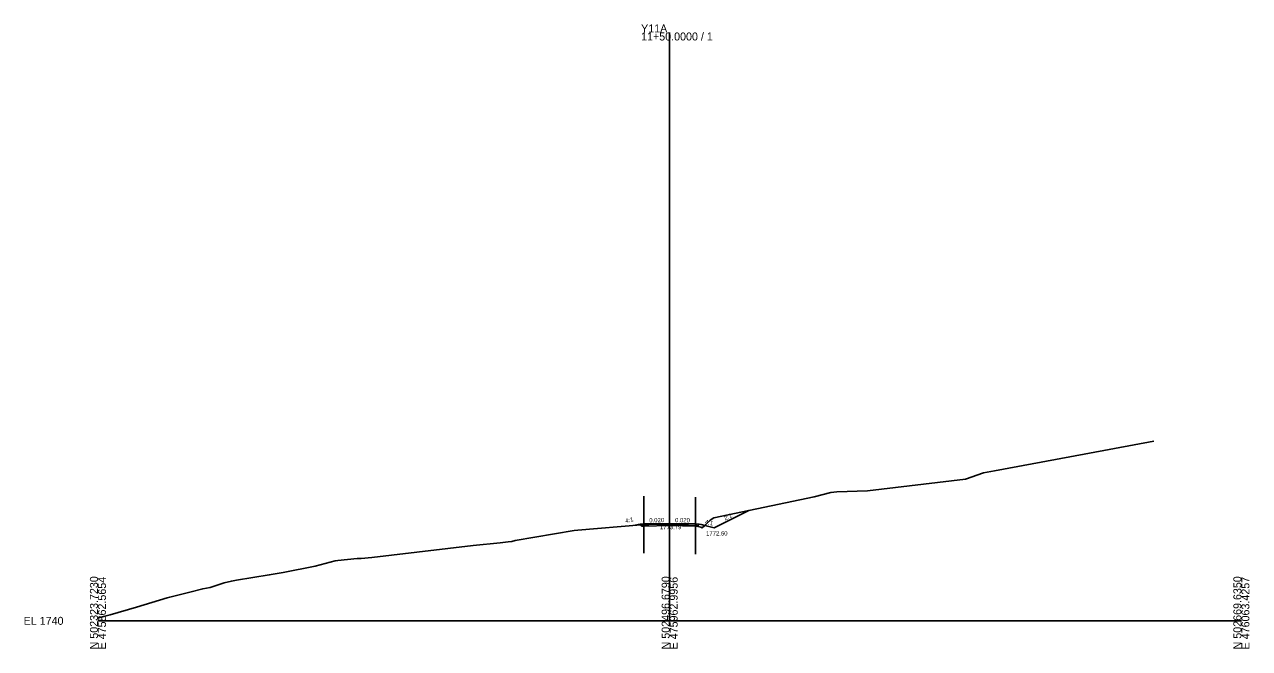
# Model space of a CAD drawing. Extents: x -26 to 403, y -10 to 5098.
# Drawn here: x -25.7 to 402.8, y 1490.3 to 1708.8 of the extents above; entities that cross this region are included whole.
import ezdxf

# ---------------------------------------------------------------- set-up
doc = ezdxf.new("R2010")
doc.units = 0
for name, color, linetype in [('Exist Cross Section Cell', 7, 'Continuous'), ('Exist XS Center Line Elevation Label', 7, 'Continuous'), ('Exist XS Ground Line', 7, 'Continuous'), ('Prop XS Ditch Slope Text', 7, 'Continuous'), ('Prop XS Ditch Standard Text', 7, 'Continuous'), ('Prop XS Dump Level', 7, 'Continuous'), ('Prop XS Earthwork Shape', 7, 'Continuous'), ('Prop XS EOT Tick Mark', 7, 'Continuous'), ('Prop XS Finish Grade', 7, 'Continuous'), ('Prop XS Finish Grade Earthwork', 7, 'Continuous'), ('Prop XS Finish Grade Pavement', 7, 'Continuous'), ('Prop XS Hydro Typical Ditch Data', 7, 'Continuous'), ('Prop XS Pvmt Edge Slope', 7, 'Continuous'), ('Prop XS SE Text', 7, 'Continuous'), ('Prop XS Shoulder Borrow Shape', 7, 'Continuous'), ('Prop XS Side Slope Text', 7, 'Continuous'), ('Prop XS Subgrade Earthwork', 7, 'Continuous'), ('Scratch_Level_5', 7, 'Continuous')]:
    doc.layers.add(name, color=color, linetype=linetype)

msp = doc.modelspace()

# ---------------------------------------------------------------- linework, layer by layer
at = {"layer": 'Exist Cross Section Cell'}
for p, q in [((200, 1500), (200, 1705.98)), ((0, 1500), (200, 1500)), ((200, 1500), (400, 1500))]:
    msp.add_line(p, q, dxfattribs=at)
at = {"layer": 'Exist XS Ground Line'}
msp.add_lwpolyline([(0, 1501.01), (0.33, 1501.08), (1.97, 1501.51), (4.29, 1502.13), (13.53, 1504.8), (24.21, 1508.07), (25.1, 1508.33), (32.09, 1509.99), (36.67, 1511.26), (39.21, 1511.71), (44.13, 1513.27), (46.72, 1513.9), (48.52, 1514.27), (59.91, 1516.09), (64.74, 1516.96), (75.99, 1519.19), (82.93, 1520.96), (83.96, 1521.13), (90.63, 1521.8), (92.06, 1521.84), (95.76, 1522.21), (102.66, 1522.98), (131.21, 1526.32), (140.76, 1527.35), (143.51, 1527.65), (144.78, 1527.79), (145.95, 1528.07), (166.63, 1531.67), (167.88, 1531.79), (189.95, 1533.66), (195.56, 1533.8), (198.46, 1533.87), (200, 1533.79), (208.8, 1533.35), (209.94, 1533.06), (210.85, 1532.76), (211.39, 1532.6), (214.18, 1535.23), (215.42, 1536.06), (250.5, 1543.44), (256.42, 1544.92), (258.52, 1545.16), (269.15, 1545.56), (303.48, 1549.6), (309.76, 1551.81), (313.64, 1552.56), (339.98, 1557.38), (369.37, 1562.86)], dxfattribs=at)
at = {"layer": 'Prop XS Dump Level'}
for p, q in [((191, 1533.91), (200, 1534.09)), ((200, 1534.09), (209, 1533.91))]:
    msp.add_line(p, q, dxfattribs=at)
at = {"layer": 'Prop XS Earthwork Shape'}
for points in [[(215.6, 1532.6), (227.7, 1538.65), (215.42, 1536.06), (214.18, 1535.23), (212.28, 1533.43)], [(189, 1533.75), (187.99, 1533.5), (189.81, 1533.65), (189.66, 1533.8)], [(189.81, 1533.65), (189.95, 1533.66), (195.56, 1533.8), (198.46, 1533.87), (200, 1533.79), (208.8, 1533.35), (209.4, 1533.19), (209, 1533.2), (200, 1533.38), (191, 1533.2), (190.28, 1533.19)], [(211, 1533.75), (212.28, 1533.43), (211.39, 1532.6), (210.85, 1532.76), (209.94, 1533.06), (209.4, 1533.19), (209.72, 1533.19), (210.34, 1533.8)]]:
    msp.add_lwpolyline(points, close=True, dxfattribs=at)
at = {"layer": 'Prop XS EOT Tick Mark'}
for p, q in [((191, 1533.91), (191, 1534.91)), ((209, 1533.91), (209, 1534.91))]:
    msp.add_line(p, q, dxfattribs=at)
at = {"layer": 'Prop XS Finish Grade'}
for p, q in [((191, 1533.91), (189.66, 1533.8)), ((209, 1533.91), (210.34, 1533.8))]:
    msp.add_line(p, q, dxfattribs=at)
at = {"layer": 'Prop XS Finish Grade Earthwork'}
for p, q in [((215.6, 1532.6), (227.7, 1538.65)), ((189, 1533.75), (187.99, 1533.5)), ((189.66, 1533.8), (189, 1533.75)), ((210.34, 1533.8), (211, 1533.75)), ((211, 1533.75), (215.6, 1532.6))]:
    msp.add_line(p, q, dxfattribs=at)
at = {"layer": 'Prop XS Finish Grade Pavement'}
for p, q in [((191, 1533.91), (200, 1534.09)), ((200, 1534.09), (209, 1533.91))]:
    msp.add_line(p, q, dxfattribs=at)
at = {"layer": 'Prop XS Hydro Typical Ditch Data'}
for p, q in [((215.6, 1532.6), (227.7, 1538.65)), ((211, 1533.75), (215.6, 1532.6))]:
    msp.add_line(p, q, dxfattribs=at)
at = {"layer": 'Prop XS Pvmt Edge Slope'}
for p, q in [((191, 1533.91), (190.28, 1533.19)), ((209, 1533.91), (209.72, 1533.19))]:
    msp.add_line(p, q, dxfattribs=at)
at = {"layer": 'Prop XS Shoulder Borrow Shape'}
for points in [[(191, 1533.91), (190.28, 1533.19), (189.66, 1533.8)], [(209.72, 1533.19), (210.34, 1533.8), (209, 1533.91)]]:
    msp.add_lwpolyline(points, close=True, dxfattribs=at)
at = {"layer": 'Prop XS Subgrade Earthwork'}
for p, q in [((190.28, 1533.19), (189.66, 1533.8)), ((191, 1533.2), (190.28, 1533.19)), ((200, 1533.38), (191, 1533.2)), ((209, 1533.2), (200, 1533.38)), ((209, 1533.2), (209.72, 1533.19)), ((209.72, 1533.19), (210.34, 1533.8))]:
    msp.add_line(p, q, dxfattribs=at)
at = {"layer": 'Scratch_Level_5'}
for p, q in [((191, 1543.69), (191, 1523.69)), ((209, 1543.3), (209, 1523.3))]:
    msp.add_line(p, q, dxfattribs=at)

# ---------------------------------------------------------------- texts
at = {"layer": 'Exist Cross Section Cell'}
for s, p in [('Y11A', (190, 1705.98)), ('11+50.0000 / 1', (190, 1703.18)), ('EL 1740', (-26, 1498.6))]:
    msp.add_text(s, height=2.8, dxfattribs=at).set_placement(p)
for s, p in [('N 502323.7230', (0, 1490)), ('E 475862.5654', (2.8, 1490)), ('N 502496.6790', (200, 1490)), ('E 475962.9956', (202.8, 1490)), ('N 502669.6350', (400, 1490)), ('E 476063.4257', (402.8, 1490))]:
    msp.add_text(s, height=2.8, rotation=90, dxfattribs=at).set_placement(p)
at = {"layer": 'Exist XS Center Line Elevation Label'}
msp.add_text('1773.79', height=1.5, dxfattribs=at).set_placement((196.61, 1532.08))
at = {"layer": 'Prop XS Ditch Slope Text'}
for rotation, p in [(14.0362, (184.64, 1534.21)), (345.9638, (212.23, 1534.02))]:
    msp.add_text('4:1', height=1.5, rotation=rotation, dxfattribs=at).set_placement(p)
at = {"layer": 'Prop XS Ditch Standard Text'}
msp.add_text('1772.60', height=1.5, dxfattribs=at).set_placement((212.75, 1529.87))
at = {"layer": 'Prop XS Dump Level'}
for p in [(189, 1533.71), (211, 1533.71)]:
    msp.add_text('Case1', height=0.04, dxfattribs=at).set_placement(p)
at = {"layer": 'Prop XS SE Text'}
for rotation, p in [(1.1458, (192.88, 1534.45)), (358.8542, (201.88, 1534.55))]:
    msp.add_text('0.020', height=1.5, rotation=rotation, dxfattribs=at).set_placement(p)
at = {"layer": 'Prop XS Side Slope Text'}
msp.add_text('2:1', height=1.5, rotation=26.5651, dxfattribs=at).set_placement((219.43, 1535.1))

doc.saveas('drawing.dxf')
